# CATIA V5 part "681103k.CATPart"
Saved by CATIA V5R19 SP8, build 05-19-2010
Part number: 681103 ADNP-25-60-I-P-A---(KS)
Definition: Cadenas PARTsolutions
Description: NT
Property "NN": "ADNP-(KS)"
Property "NT": "Compact cylinder"
Property "NB": "681103 ADNP-25-60-I-P-A---(KS)"
Property "NBSYN": "$TNR. $TYP.---(KS)"
Property "LINA": "681103 ADNP-25-60-I-P-A"
Property "TNR": "681103"
Property "TYP": "ADNP-25-60-I-P-A"
Property "KDM": "25.000"
Property "HUB": "60.000"
Property "VERS": "1.000"
Property "G": "12.000"
Property "A": "16.000"
Property "AF": "14.000"
Property "BG": "19.500"
Property "KF": "M6"
Property "KFNDM": "6.000"
Property "KFKDM": "4.917"
Property "KK": "M8"
Property "KKP": "1.250"
Property "KKNDM": "8.000"
Property "KKKDM": "6.647"
Property "L12": "4.200"
Property "MM": "10.000"
Property "SW": "8.000"
Property "T4": "2.600"
Property "WH": "5.500"
Property "VERS2": "2.000"
Property "L2": "39.000"
Property "PL": "6.000"
Property "VENDOR": "FESTO"
Property "SUPPLIER": "FESTO"
Property "ARTICLENO": "NB"
Property "BOMINFO": "LINA"
Property "CREATOR": "CADENAS GmbH"
Bounding box of the stored display mesh (mm): x -12.497 to 12.497, y -12.358 to 12.358, z -87 to 5.5
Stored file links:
  C:\Users\Schrotter\Desktop\Neuer Ordner (2)\681103k.CATPart
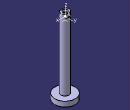
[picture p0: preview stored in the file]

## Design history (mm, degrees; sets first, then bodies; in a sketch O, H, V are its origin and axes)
AxisSystem1: origin (0, 0, 0), X (1, 0, 0), Y (0, 1, 0), Z (0, 0, 1)
Set1
  Point1: (0, 0, 0)
  Point2: (0, 0, -1)
  Point3: (0, 1, 0)
  Plane1: type 3Points, Element1 Point1, Element2 Point2, Element3 Point3
  Point4: (0, 0, 5.5)
  Point5: (1, 0, 5.5)
  Point6: (0, 1, 5.5)
  Plane2: type 3Points, Element1 Point4, Element2 Point5, Element3 Point6
  Point7: (0, 0, 0)
  Point8: (0, 0, -1)
  Point9: (0, 1, 0)
  Plane3: type 3Points, Element1 Point7, Element2 Point8, Element3 Point9
Body1 (main body)
  Sketch1 on Plane1, origin (0, 0, 0), H (0, 0, -1), V (0, 1, 0)
    point P1 (-5.5, 0)
    point P2 (-5.5, 5)
    line L1 (-5.5, 0) -> (-5.5, 5)
    point P3 (-5.5, 5)
    point P4 (80.75, 5)
    line L2 (-5.5, 5) -> (80.75, 5)
    point P5 (80.75, 5)
    point P6 (80.75, 12.5)
    line L3 (80.75, 5) -> (80.75, 12.5)
    point P7 (80.75, 12.5)
    point P8 (87, 12.5)
    line L4 (80.75, 12.5) -> (87, 12.5)
    point P9 (87, 12.5)
    point P10 (87, 0)
    line L5 (87, 12.5) -> (87, 0)
    point P11 (87, 0)
    point P12 (-5.5, 0)
    line L6 (87, 0) -> (-5.5, 0)
    point P13 (87, 0)
    point P14 (-5.5, 0)
    axis line L7 (87, 0) -> (-5.5, 0)
    coincidence: P1 P12, P2 P3, P4 P5, P6 P7, P8 P9, P10 P11
  Shaft1: profile Sketch1, axis Sketch1.L7, angle 0, second angle 360
  Sketch2 on Plane2, origin (0, 0, 5.5), H (1, 0, 0), V (0, 1, 0)
    point P1 (-20, -14)
    point P2 (10, -14)
    line L1 (-20, -14) -> (10, -14)
    point P3 (10, -14)
    point P4 (10, -4)
    line L2 (10, -14) -> (10, -4)
    point P5 (10, -4)
    point P6 (-10, -4)
    line L3 (10, -4) -> (-10, -4)
    point P7 (-10, -4)
    point P8 (-10, 4)
    line L4 (-10, -4) -> (-10, 4)
    point P9 (-10, 4)
    point P10 (10, 4)
    line L5 (-10, 4) -> (10, 4)
    point P11 (10, 4)
    point P12 (10, 14)
    line L6 (10, 4) -> (10, 14)
    point P13 (10, 14)
    point P14 (-20, 14)
    line L7 (10, 14) -> (-20, 14)
    point P15 (-20, 14)
    point P16 (-20, -14)
    line L8 (-20, 14) -> (-20, -14)
    coincidence: P1 P16, P2 P3, P4 P5, P6 P7, P8 P9, P10 P11, P12 P13, P14 P15
  Pocket1: profile Sketch2, direction (0, 0, -1), length 4.2
  Sketch3 on Plane3, origin (0, 0, 0), H (0, 0, -1), V (0, 1, 0)
    point P1 (-5.5, 0)
    point P2 (-5.5, 3)
    line L1 (-5.5, 0) -> (-5.5, 3)
    point P3 (-5.5, 3)
    point P4 (-2.9, 3)
    line L2 (-5.5, 3) -> (-2.9, 3)
    point P5 (-2.9, 3)
    point P6 (-2.3585, 2.4585)
    line L3 (-2.9, 3) -> (-2.3585, 2.4585)
    point P7 (-2.3585, 2.4585)
    point P8 (11.7473, 2.4585)
    line L4 (-2.3585, 2.4585) -> (11.7473, 2.4585)
    point P9 (11.7473, 2.4585)
    point P10 (13.1667, 0)
    line L5 (11.7473, 2.4585) -> (13.1667, 0)
    point P11 (13.1667, 0)
    point P12 (-5.5, 0)
    line L6 (13.1667, 0) -> (-5.5, 0)
    point P13 (13.1667, 0)
    point P14 (-5.5, 0)
    axis line L7 (13.1667, 0) -> (-5.5, 0)
    coincidence: P1 P12, P2 P3, P4 P5, P6 P7, P8 P9, P10 P11
  Groove1: profile Sketch3, axis Sketch3.L7, angle 0, second angle 360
